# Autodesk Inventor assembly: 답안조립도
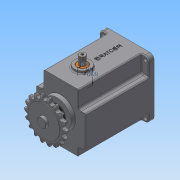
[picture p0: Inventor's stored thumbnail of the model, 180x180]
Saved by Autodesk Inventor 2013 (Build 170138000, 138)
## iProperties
Created: 2016-05
Part Number: 답안조립도
Document SubType Name: Assembly
Designer: Administrator
Author: Administrator
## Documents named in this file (16)
- C:\Users\Administrator\Desktop\360508V1009\답안조립도.iam
- C:\Users\Administrator\Desktop\360508V1009\본체.ipt
- C:\Users\Administrator\Desktop\360508V1009\오일실 8 22 7.ipt
- C:\Users\Administrator\Desktop\360508V1009\오일실 17 32 8.ipt
- C:\Users\Administrator\Desktop\360508V1009\커버.ipt
- C:\Users\Administrator\Desktop\360508V1009\베어링 608.ipt
- C:\Users\Administrator\Desktop\360508V1009\메인축.ipt
- C:\Users\Administrator\Desktop\360508V1009\서브축.ipt
- C:\Users\Administrator\Desktop\360508V1009\베어링 6003.ipt
- C:\Users\Administrator\Desktop\360508V1009\스프로킷.ipt
- C:\Users\Administrator\Desktop\360508V1009\키 5 x 5 x 18.ipt
- C:\Users\Administrator\Desktop\360508V1009\멈춤나사 M3x8.ipt
- C:\Users\Administrator\Desktop\360508V1009\부시.ipt
- C:\Users\Administrator\Desktop\360508V1009\슬라이더.ipt
- C:\Users\Administrator\Desktop\360508V1009\가변스프링.ipt
- C:\Users\Administrator\Desktop\360508V1009\볼트 M4 x 10.ipt
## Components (3 placed, 2 different names)
1. 가변스프링:1
2. ISO 4762 M4 x 10:1
3. ISO 4762 M4 x 10:2
